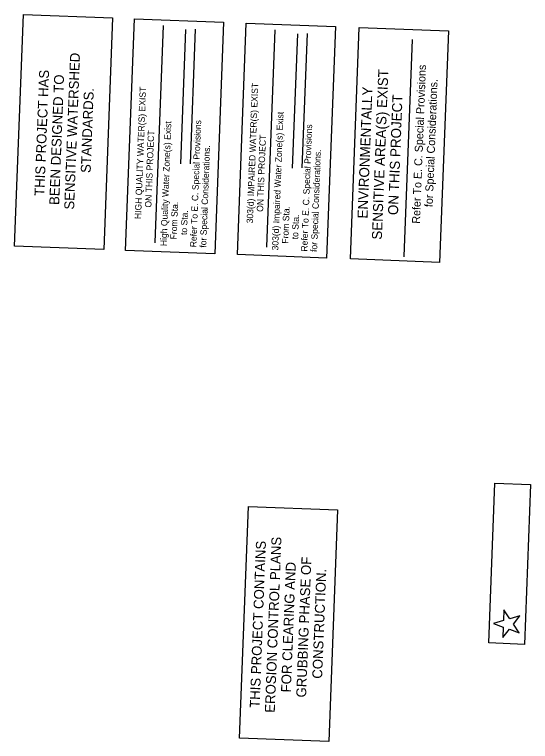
# Model space of a CAD drawing. Extents: x 1654773 to 2116434, y 680831 to 888488.
# Drawn here: x 2096814 to 2101083, y 713757 to 719770 of the extents above; entities that cross this region are included whole.
import ezdxf

# ---------------------------------------------------------------- set-up
doc = ezdxf.new("R2010")
doc.units = 0
for name, color, linetype in [('EC Title Sheet Consultant CELL', 7, 'Continuous'), ('Prop Grid Mask', 7, 'Continuous'), ('Prop RDY Traffic Signal CELL', 7, 'Continuous')]:
    doc.layers.add(name, color=color, linetype=linetype)

msp = doc.modelspace()

# ---------------------------------------------------------------- linework, layer by layer
at = {"layer": 'EC Title Sheet Consultant CELL'}
for p, q in [((2098268.5, 718536.1), (2098311.2, 719647.4)), ((2098188.5, 718533.9), (2098231.2, 719645.5)), ((2099114.2, 718498.4), (2099156.8, 719609.9)), ((2099194.1, 718500.5), (2099236.9, 719611.9))]:
    msp.add_line(p, q, dxfattribs=at)
for points in [[(2096813.6, 717854.4), (2096887.1, 719769.5), (2097625.1, 719741.1), (2097551.6, 717826.1)], [(2097732.1, 717819.1), (2097805.6, 719734.3), (2098543.6, 719705.8), (2098470.1, 717790.8)], [(2098657.7, 717783.6), (2098731.2, 719698.7), (2099469.2, 719670.3), (2099395.7, 717755.3)], [(2099593.3, 717747.7), (2099666.8, 719662.8), (2100404.8, 719634.4), (2100331.3, 717719.4)], [(2098675.5, 713785.9), (2098748.8, 715700.9), (2099486.9, 715672.6), (2099413.5, 713757.4)]]:
    msp.add_lwpolyline(points, close=True, dxfattribs=at)
for points in [[(2097976.5, 717880.3), (2097976.6, 717883.8), (2098045.5, 719677.8)], [(2098902.1, 717844.8), (2098902.3, 717848.3), (2098971.1, 719642.2)], [(2100038.9, 717766), (2100039, 717769.3), (2100107.9, 719563.6)]]:
    msp.add_lwpolyline(points, dxfattribs=at)
at = {"layer": 'Prop Grid Mask'}
msp.add_lwpolyline([(2100737.5, 714571.8), (2100788.3, 715895), (2101083.1, 715883.7), (2101032.3, 714560.5)], close=True, dxfattribs=at)
at = {"layer": 'Prop RDY Traffic Signal CELL'}
msp.add_lwpolyline([(2100857.7, 714703.9), (2100854.4, 714616.9), (2100908.2, 714685.3), (2100990.1, 714655.2), (2100941.5, 714727.7), (2100995.4, 714796.3), (2100911.6, 714772.5), (2100863.1, 714844.9), (2100859.8, 714757.8), (2100775.8, 714734), (2100857.7, 714703.9)], dxfattribs=at)

# ---------------------------------------------------------------- texts
at = {"layer": 'EC Title Sheet Consultant CELL'}
for s, height, p in [('SENSITIVE WATERSHED', 81.637, (2097306, 718154.9)), ('Refer To E. C. Special Provisions', 66.324, (2100168.2, 718038.5)), ('THIS PROJECT HAS', 81.637, (2097059.9, 718268.2)), ('SENSITIVE AREA(S) EXIST', 82.907, (2099853.2, 717906.3)), ('BEEN DESIGNED TO ', 81.637, (2097182.4, 718193.2)), ('for Special Considerations.', 66.324, (2100273.9, 718175.8)), ('HIGH QUALITY WATER(S) EXIST', 53.06, (2097860.5, 718076.8)), ('303(d) IMPAIRED WATER(S) EXIST', 53.06, (2098786.4, 718041.4)), ('ENVIRONMENTALLY ', 82.907, (2099734.3, 718081.1)), ('STANDARDS.', 81.64, (2097443, 718458.2)), ('ON THIS PROJECT', 82.907, (2099986.4, 718109.4)), ('303(d) Impaired Water Zone(s) Exist', 53.06, (2098995.9, 717817.6)), ('High Quality Water Zone(s) Exist', 53.06, (2098071.7, 717853.2)), ('Refer To E. C. Special Provisions', 53.06, (2098318.2, 717843.7)), ('     ON THIS PROJECT', 53.06, (2097942, 718073.6)), ('Refer To E. C. Special Provisions', 53.06, (2099236.6, 717808.3)), ('     ON THIS PROJECT', 53.06, (2098866.7, 718038.3)), ('for Special Considerations.', 53.06, (2098399.7, 717840.6)), ('for Special Considerations.', 53.06, (2099316.9, 717805.2)), ('   From Sta.                      ', 53.06, (2098153.2, 717850)), ('     to Sta.', 53.06, (2098236.6, 717846.8)), ('   From Sta.                      ', 53.06, (2099076.1, 717814.5)), ('     to Sta.', 53.06, (2099156.4, 717811.4)), ('EROSION CONTROL PLANS', 81.637, (2098966.7, 713993.5)), ('THIS PROJECT CONTAINS', 81.637, (2098841.1, 714033.6)), ('GRUBBING PHASE OF', 81.637, (2099225.8, 714119.9)), ('FOR CLEARING AND', 81.637, (2099100.1, 714161.8)), ('CONSTRUCTION.', 81.637, (2099358.8, 714274.8))]:
    msp.add_text(s, height=height, rotation=87.80202, dxfattribs=at).set_placement(p)

doc.saveas('drawing.dxf')
